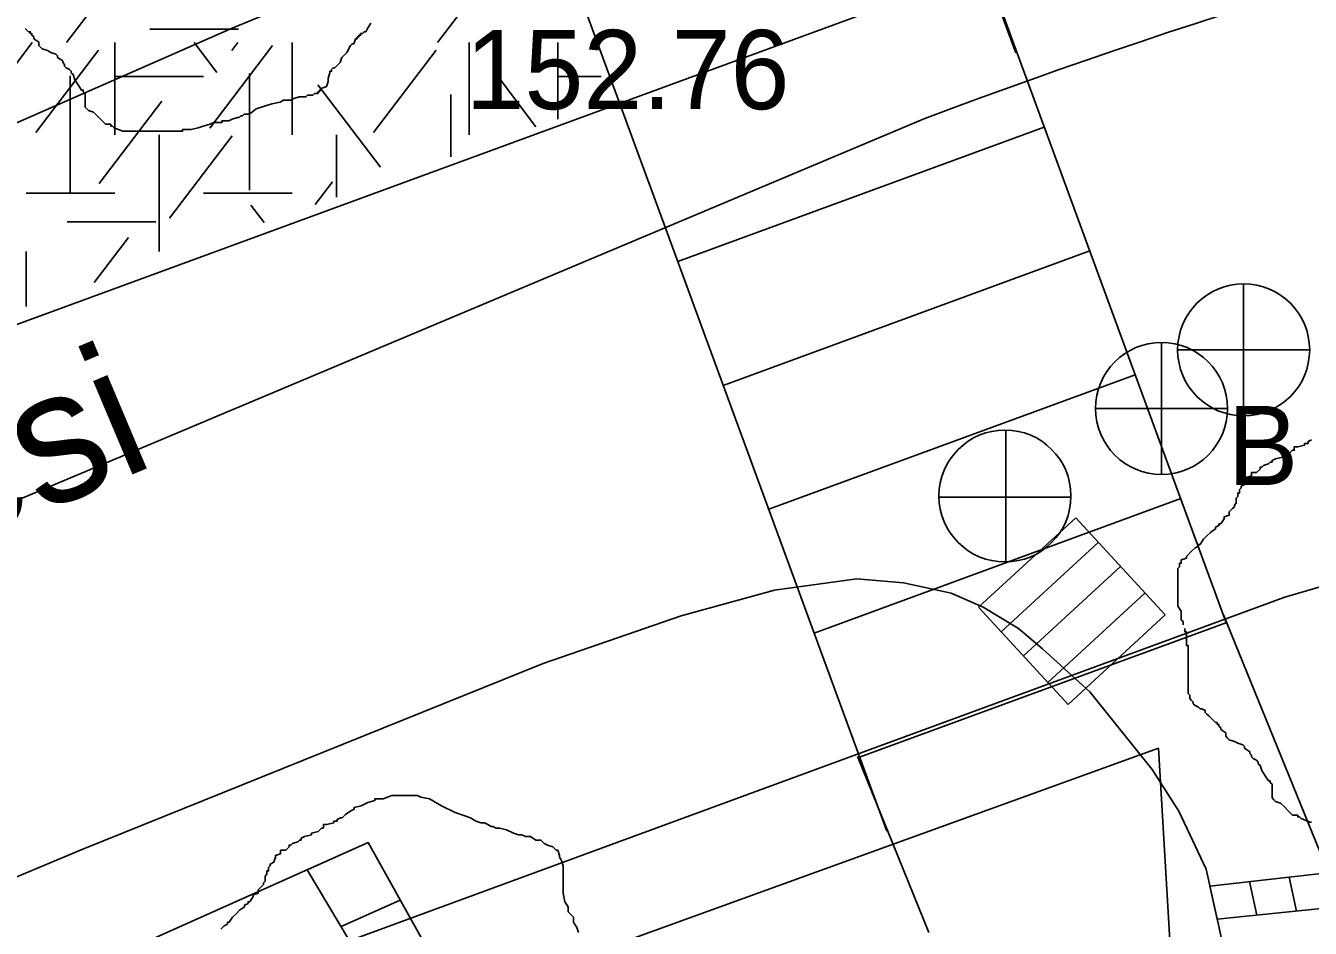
# Model space of a CAD drawing. Extents: x 419101 to 420177, y 4451541 to 4452254.
# Drawn here: x 419828.86 to 419848.32, y 4451817.27 to 4451830.95 of the extents above; entities that cross this region are included whole.
import ezdxf

# ---------------------------------------------------------------- set-up
doc = ezdxf.new("R2010")
doc.units = 0
for name, color, linetype in [('2_KADASTRO', 7, 'Continuous'), ('3_HALİHAZIR', 7, 'Continuous'), ('Level 3', 7, 'Continuous'), ('Level 41', 7, 'Continuous'), ('Level 60', 7, 'Continuous'), ('Level 62', 7, 'Continuous')]:
    doc.layers.add(name, color=color, linetype=linetype)

msp = doc.modelspace()

# ---------------------------------------------------------------- linework, layer by layer
at = {"layer": '2_KADASTRO'}
msp.add_lwpolyline([(419789.195, 4451663.821), (419792.466, 4451722.195), (419796.208, 4451788.966), (419796.952, 4451802.25), (419802.028, 4451804.087), (419846.019, 4451820.004), (419846.711, 4451808.426), (419850.52, 4451780.325), (419850.846, 4451775.043), (419851.91, 4451757.789), (419863.818, 4451701.263), (419862.735, 4451692.788), (419853.795, 4451660.742)], close=True, dxfattribs=at)
at = {"layer": '3_HALİHAZIR'}
for p, q in [((419847.31, 4451827.04), (419847.31, 4451825.04)), ((419846.066, 4451826.153), (419846.066, 4451824.153)), ((419846.31, 4451826.04), (419848.31, 4451826.04)), ((419845.066, 4451825.153), (419847.066, 4451825.153)), ((419843.709, 4451822.818), (419843.709, 4451824.818)), ((419842.689, 4451823.808), (419844.689, 4451823.808)), ((419844.766, 4451823.494), (419843.295, 4451822.14)), ((419844.766, 4451823.494), (419843.295, 4451822.14)), ((419846.121, 4451822.023), (419844.766, 4451823.494)), ((419846.121, 4451822.023), (419844.766, 4451823.494)), ((419843.636, 4451821.768), (419845.108, 4451823.123)), ((419843.972, 4451821.404), (419845.443, 4451822.758)), ((419844.343, 4451821.001), (419845.814, 4451822.355)), ((419843.295, 4451822.14), (419844.649, 4451820.668)), ((419843.295, 4451822.14), (419844.649, 4451820.668)), ((419844.649, 4451820.668), (419846.121, 4451822.023)), ((419844.649, 4451820.668), (419846.121, 4451822.023)), ((419847.398, 4451817.983), (419847.511, 4451817.472)), ((419847.997, 4451818.051), (419848.112, 4451817.534)), ((419833.636, 4451817.299), (419834.532, 4451817.7))]:
    msp.add_line(p, q, dxfattribs=at)
for points in [[(419841.024, 4451851.727), (419839.922, 4451837.507), (419839.676, 4451834.933), (419839.599, 4451834.673), (419839.324, 4451834.19), (419839.045, 4451833.925), (419838.738, 4451833.693), (419831.983, 4451830.915), (419822.667, 4451826.822)], [(419819.946, 4451814.381), (419829.721, 4451818.474), (419836.698, 4451821.289), (419838.786, 4451822.011), (419840.202, 4451822.4), (419841.449, 4451822.571), (419842.156, 4451822.512), (419842.877, 4451822.354), (419843.361, 4451822.14), (419843.897, 4451821.816), (419844.264, 4451821.509), (419844.979, 4451820.857), (419845.924, 4451819.679), (419846.329, 4451819.051), (419846.743, 4451818.168), (419847.007, 4451816.982)], [(419797.913, 4451802.315), (419813.395, 4451809.339), (419834.048, 4451818.574)]]:
    msp.add_lwpolyline(points, dxfattribs=at)
for points in [[(419833.122, 4451818.16), (419834.048, 4451818.574), (419834.973, 4451816.905), (419842.377, 4451813.448), (419845.895, 4451813.483), (419846.024, 4451812.471), (419842.025, 4451812.598), (419834.391, 4451816.032)], [(419846.911, 4451817.411), (419846.799, 4451817.915), (419852.975, 4451818.615), (419853.027, 4451818.037)]]:
    msp.add_lwpolyline(points, close=True, dxfattribs=at)
for centre in [(419847.31, 4451826.04), (419846.066, 4451825.153), (419843.694, 4451823.826)]:
    msp.add_circle(centre, 1, dxfattribs=at)
at = {"layer": 'Level 3'}
for points in [[(419830.353, 4451829.355), (419830.327, 4451829.355), (419830.197, 4451829.407), (419830.171, 4451829.433), (419830.145, 4451829.433), (419830.145, 4451829.459), (419830.067, 4451829.459), (419830.015, 4451829.511), (419829.938, 4451829.589), (419829.886, 4451829.641), (419829.808, 4451829.667), (419829.782, 4451829.693), (419829.756, 4451829.719), (419829.756, 4451829.745), (419829.756, 4451829.823), (419829.756, 4451829.901), (419829.756, 4451829.926), (419829.73, 4451829.952), (419829.73, 4451829.978), (419829.704, 4451829.978), (419829.652, 4451830.056), (419829.6, 4451830.134), (419829.574, 4451830.212), (419829.548, 4451830.238), (419829.548, 4451830.264), (419829.522, 4451830.29), (419829.471, 4451830.316), (419829.445, 4451830.342), (419829.445, 4451830.368), (419829.419, 4451830.394), (419829.419, 4451830.42), (419829.341, 4451830.472), (419829.341, 4451830.498), (419829.315, 4451830.524), (419829.237, 4451830.55), (419829.185, 4451830.576), (419829.107, 4451830.602), (419829.081, 4451830.628), (419829.056, 4451830.654), (419829.056, 4451830.68), (419829.056, 4451830.706), (419828.978, 4451830.757), (419828.978, 4451830.783), (419828.952, 4451830.809), (419828.952, 4451830.835), (419828.926, 4451830.835), (419828.926, 4451830.861), (419828.9, 4451830.861), (419828.874, 4451830.887), (419828.848, 4451830.913)], [(419834.088, 4451830.991), (419834.036, 4451830.913), (419834.01, 4451830.861), (419833.984, 4451830.861), (419833.958, 4451830.835), (419833.932, 4451830.835), (419833.932, 4451830.809), (419833.906, 4451830.809), (419833.906, 4451830.783), (419833.881, 4451830.783), (419833.881, 4451830.757), (419833.855, 4451830.757), (419833.829, 4451830.68), (419833.803, 4451830.68), (419833.777, 4451830.654), (419833.725, 4451830.55), (419833.647, 4451830.472), (419833.621, 4451830.394), (419833.543, 4451830.316), (419833.517, 4451830.316), (419833.491, 4451830.29), (419833.491, 4451830.264), (419833.465, 4451830.264), (419833.465, 4451830.238), (419833.44, 4451830.16), (419833.44, 4451830.108), (419833.414, 4451830.03), (419833.336, 4451830.004), (419833.336, 4451829.978), (419833.31, 4451829.978), (419833.31, 4451829.952), (419833.284, 4451829.952), (419833.284, 4451829.926), (419833.258, 4451829.926), (419833.232, 4451829.926), (419833.206, 4451829.901), (419833.18, 4451829.901), (419833.154, 4451829.901), (419833.128, 4451829.901), (419833.102, 4451829.875), (419833.076, 4451829.875), (419833.05, 4451829.875), (419833.024, 4451829.875), (419832.999, 4451829.875), (419832.921, 4451829.849), (419832.869, 4451829.823), (419832.791, 4451829.823), (419832.765, 4451829.823), (419832.713, 4451829.797), (419832.584, 4451829.771), (419832.35, 4451829.693), (419832.246, 4451829.615), (419832.168, 4451829.615), (419832.143, 4451829.589), (419832.117, 4451829.589), (419832.091, 4451829.563), (419832.065, 4451829.563), (419831.987, 4451829.537), (419831.935, 4451829.511), (419831.909, 4451829.511), (419831.883, 4451829.511), (419831.857, 4451829.511), (419831.831, 4451829.511), (419831.831, 4451829.485), (419831.805, 4451829.485), (419831.779, 4451829.485), (419831.702, 4451829.485), (419831.65, 4451829.459), (419831.546, 4451829.433), (419831.468, 4451829.407), (419831.364, 4451829.381), (419831.312, 4451829.381), (419831.286, 4451829.381), (419831.261, 4451829.381), (419831.235, 4451829.381), (419831.235, 4451829.355), (419831.209, 4451829.355), (419831.183, 4451829.355), (419831.157, 4451829.355), (419831.131, 4451829.355), (419831.105, 4451829.355), (419831.079, 4451829.355), (419831.053, 4451829.355), (419831.027, 4451829.355), (419831.001, 4451829.355), (419830.923, 4451829.355), (419830.871, 4451829.355), (419830.794, 4451829.355), (419830.742, 4451829.355), (419830.716, 4451829.355), (419830.69, 4451829.355), (419830.638, 4451829.355), (419830.56, 4451829.355), (419830.534, 4451829.355), (419830.482, 4451829.355), (419830.456, 4451829.355), (419830.404, 4451829.355), (419830.379, 4451829.355), (419830.353, 4451829.355)], [(419846.391, 4451821.872), (419846.391, 4451821.898), (419846.391, 4451821.923), (419846.365, 4451821.949), (419846.365, 4451821.975), (419846.365, 4451822.001), (419846.365, 4451822.027), (419846.365, 4451822.053), (419846.365, 4451822.079), (419846.313, 4451822.157), (419846.313, 4451822.235), (419846.313, 4451822.261), (419846.313, 4451822.339), (419846.313, 4451822.417), (419846.313, 4451822.443), (419846.313, 4451822.469), (419846.313, 4451822.495), (419846.313, 4451822.521), (419846.313, 4451822.547), (419846.313, 4451822.573), (419846.313, 4451822.599), (419846.313, 4451822.625), (419846.313, 4451822.651), (419846.313, 4451822.729), (419846.339, 4451822.754), (419846.339, 4451822.78), (419846.339, 4451822.806), (419846.365, 4451822.806), (419846.365, 4451822.832), (419846.365, 4451822.858), (419846.443, 4451822.884), (419846.443, 4451822.91), (419846.521, 4451822.988), (419846.573, 4451823.04), (419846.624, 4451823.066), (419846.624, 4451823.092), (419846.65, 4451823.092), (419846.702, 4451823.17), (419846.754, 4451823.222), (419846.806, 4451823.274), (419846.884, 4451823.326), (419846.884, 4451823.352), (419846.936, 4451823.378), (419846.936, 4451823.404), (419846.962, 4451823.404), (419847.014, 4451823.482), (419847.014, 4451823.508), (419847.091, 4451823.534), (419847.091, 4451823.559), (419847.091, 4451823.585), (419847.143, 4451823.637), (419847.169, 4451823.663), (419847.169, 4451823.689), (419847.195, 4451823.715), (419847.195, 4451823.741), (419847.195, 4451823.767), (419847.195, 4451823.793), (419847.221, 4451823.819), (419847.221, 4451823.845), (419847.221, 4451823.871), (419847.247, 4451823.871), (419847.247, 4451823.897), (419847.247, 4451823.923), (419847.273, 4451823.949), (419847.273, 4451823.975), (419847.325, 4451824.001), (419847.351, 4451824.079), (419847.351, 4451824.105), (419847.429, 4451824.131), (419847.429, 4451824.157), (419847.429, 4451824.183), (419847.506, 4451824.183), (419847.558, 4451824.235), (419847.558, 4451824.261), (419847.584, 4451824.261), (419847.61, 4451824.287), (419847.688, 4451824.313), (419847.714, 4451824.339), (419847.74, 4451824.339), (419847.74, 4451824.365), (419847.792, 4451824.39), (419847.896, 4451824.416), (419847.896, 4451824.442), (419847.999, 4451824.468), (419848.051, 4451824.52), (419848.077, 4451824.52), (419848.077, 4451824.546), (419848.077, 4451824.572), (419848.129, 4451824.572), (419848.233, 4451824.598), (419848.233, 4451824.624), (419848.259, 4451824.624), (419848.285, 4451824.624), (419848.285, 4451824.65), (419848.337, 4451824.676)], [(419848.337, 4451818.885), (419848.311, 4451818.885), (419848.181, 4451818.937), (419848.155, 4451818.963), (419848.129, 4451818.963), (419848.129, 4451818.989), (419848.051, 4451818.989), (419847.999, 4451819.041), (419847.922, 4451819.119), (419847.87, 4451819.171), (419847.792, 4451819.197), (419847.766, 4451819.223), (419847.74, 4451819.249), (419847.74, 4451819.275), (419847.74, 4451819.353), (419847.74, 4451819.431), (419847.74, 4451819.456), (419847.714, 4451819.482), (419847.714, 4451819.508), (419847.688, 4451819.508), (419847.636, 4451819.586), (419847.584, 4451819.664), (419847.558, 4451819.742), (419847.532, 4451819.768), (419847.532, 4451819.794), (419847.506, 4451819.82), (419847.455, 4451819.846), (419847.429, 4451819.872), (419847.429, 4451819.898), (419847.403, 4451819.924), (419847.403, 4451819.95), (419847.325, 4451820.002), (419847.325, 4451820.028), (419847.299, 4451820.054), (419847.221, 4451820.08), (419847.169, 4451820.106), (419847.091, 4451820.132), (419847.065, 4451820.158), (419847.04, 4451820.184), (419847.04, 4451820.21), (419847.04, 4451820.236), (419846.962, 4451820.287), (419846.962, 4451820.313), (419846.936, 4451820.339), (419846.936, 4451820.365), (419846.91, 4451820.365), (419846.91, 4451820.391), (419846.884, 4451820.391), (419846.858, 4451820.417), (419846.832, 4451820.443), (419846.806, 4451820.469), (419846.78, 4451820.495), (419846.754, 4451820.521), (419846.728, 4451820.547), (419846.728, 4451820.573), (419846.676, 4451820.599), (419846.65, 4451820.599), (419846.624, 4451820.625), (419846.573, 4451820.651), (419846.547, 4451820.677), (419846.547, 4451820.703), (419846.521, 4451820.729), (419846.495, 4451820.755), (419846.495, 4451820.781), (419846.495, 4451820.807), (419846.469, 4451820.833), (419846.469, 4451820.859), (419846.469, 4451820.885), (419846.469, 4451820.963), (419846.469, 4451821.015), (419846.469, 4451821.041), (419846.469, 4451821.067), (419846.469, 4451821.092), (419846.469, 4451821.118), (419846.469, 4451821.144), (419846.469, 4451821.17), (419846.469, 4451821.196), (419846.469, 4451821.222), (419846.469, 4451821.248), (419846.469, 4451821.274), (419846.469, 4451821.3), (419846.469, 4451821.326), (419846.469, 4451821.352), (419846.469, 4451821.378), (419846.469, 4451821.404), (419846.469, 4451821.43), (419846.469, 4451821.508), (419846.469, 4451821.534), (419846.469, 4451821.56), (419846.443, 4451821.56), (419846.443, 4451821.586), (419846.443, 4451821.612), (419846.443, 4451821.638), (419846.443, 4451821.664), (419846.443, 4451821.69), (419846.443, 4451821.716), (419846.443, 4451821.742), (419846.443, 4451821.768), (419846.417, 4451821.768), (419846.417, 4451821.794), (419846.417, 4451821.82)], [(419833.938, 4451819.131), (419834.042, 4451819.183), (419834.145, 4451819.209), (419834.145, 4451819.235), (419834.171, 4451819.235), (419834.197, 4451819.235), (419834.275, 4451819.235), (419834.405, 4451819.287), (419834.509, 4451819.287), (419834.586, 4451819.287), (419834.638, 4451819.287), (419834.716, 4451819.287), (419834.768, 4451819.287), (419834.794, 4451819.287), (419834.846, 4451819.261), (419834.976, 4451819.235), (419835.157, 4451819.131), (419835.365, 4451819.027), (419835.598, 4451818.949), (419835.676, 4451818.897), (419835.754, 4451818.871), (419835.806, 4451818.871), (419835.858, 4451818.845), (419835.909, 4451818.819), (419835.935, 4451818.819), (419835.987, 4451818.793), (419836.039, 4451818.793), (419836.143, 4451818.767), (419836.247, 4451818.715), (419836.324, 4451818.689), (419836.376, 4451818.689), (419836.428, 4451818.663), (419836.48, 4451818.663), (419836.506, 4451818.663), (419836.584, 4451818.612), (419836.662, 4451818.612), (419836.714, 4451818.56), (419836.765, 4451818.534), (419836.843, 4451818.508), (419836.895, 4451818.456), (419836.921, 4451818.456), (419836.947, 4451818.378), (419836.947, 4451818.352), (419836.973, 4451818.3), (419836.999, 4451818.222), (419836.999, 4451818.196), (419836.999, 4451818.118), (419836.999, 4451818.066), (419836.999, 4451817.988), (419836.999, 4451817.962), (419836.999, 4451817.884), (419836.999, 4451817.807), (419837.025, 4451817.677), (419837.077, 4451817.599), (419837.077, 4451817.521), (419837.155, 4451817.443), (419837.155, 4451817.365), (419837.206, 4451817.287), (419837.232, 4451817.209)], [(419831.811, 4451817.261), (419831.863, 4451817.313), (419831.914, 4451817.339), (419831.914, 4451817.365), (419831.94, 4451817.365), (419831.992, 4451817.443), (419832.044, 4451817.495), (419832.096, 4451817.547), (419832.174, 4451817.599), (419832.174, 4451817.625), (419832.226, 4451817.651), (419832.226, 4451817.677), (419832.252, 4451817.677), (419832.304, 4451817.755), (419832.304, 4451817.781), (419832.381, 4451817.807), (419832.381, 4451817.832), (419832.381, 4451817.858), (419832.433, 4451817.91), (419832.459, 4451817.936), (419832.459, 4451817.962), (419832.485, 4451817.988), (419832.485, 4451818.014), (419832.485, 4451818.04), (419832.485, 4451818.066), (419832.511, 4451818.092), (419832.511, 4451818.118), (419832.511, 4451818.144), (419832.537, 4451818.144), (419832.537, 4451818.17), (419832.537, 4451818.196), (419832.563, 4451818.222), (419832.563, 4451818.248), (419832.615, 4451818.274), (419832.641, 4451818.352), (419832.641, 4451818.378), (419832.719, 4451818.404), (419832.719, 4451818.43), (419832.719, 4451818.456), (419832.796, 4451818.456), (419832.848, 4451818.508), (419832.848, 4451818.534), (419832.874, 4451818.534), (419832.9, 4451818.56), (419832.978, 4451818.586), (419833.004, 4451818.612), (419833.03, 4451818.612), (419833.03, 4451818.638), (419833.082, 4451818.663), (419833.186, 4451818.689), (419833.186, 4451818.715), (419833.289, 4451818.741), (419833.341, 4451818.793), (419833.367, 4451818.793), (419833.367, 4451818.819), (419833.367, 4451818.845), (419833.419, 4451818.845), (419833.523, 4451818.871), (419833.523, 4451818.897), (419833.549, 4451818.897), (419833.575, 4451818.897), (419833.575, 4451818.923), (419833.627, 4451818.949), (419833.653, 4451818.949), (419833.704, 4451819.001), (419833.782, 4451819.053), (419833.834, 4451819.079), (419833.834, 4451819.105), (419833.938, 4451819.131)]]:
    msp.add_lwpolyline(points, dxfattribs=at)
at = {"layer": 'Level 41'}
for p, q in [((419829.477, 4451830.697), (419830.306, 4451831.788)), ((419835.097, 4451830.697), (419835.634, 4451831.403)), ((419830.739, 4451830.903), (419832.082, 4451830.903)), ((419828.64, 4451830.28), (419828.957, 4451830.697)), ((419830.206, 4451830.697), (419830.206, 4451829.299)), ((419831.755, 4451830.245), (419831.411, 4451830.697)), ((419831.648, 4451829.403), (419832.598, 4451830.653)), ((419831.981, 4451830.577), (419832.072, 4451830.697)), ((419832.892, 4451830.697), (419832.892, 4451829.299)), ((419835.578, 4451830.697), (419835.578, 4451829.299)), ((419836.921, 4451830.697), (419836.921, 4451829.539)), ((419836.921, 4451830.697), (419836.921, 4451829.539)), ((419829.011, 4451829.334), (419829.96, 4451830.584)), ((419834.125, 4451829.334), (419835.074, 4451830.584)), ((419832.248, 4451830.23), (419832.248, 4451828.463)), ((419836.588, 4451829.422), (419835.973, 4451830.232)), ((419829.531, 4451830.195), (419829.531, 4451828.428)), ((419830.206, 4451830.183), (419831.549, 4451830.183)), ((419834.232, 4451828.808), (419833.283, 4451830.057)), ((419836.921, 4451830.183), (419837.575, 4451830.183)), ((419835.296, 4451829.909), (419835.296, 4451828.966)), ((419829.971, 4451828.562), (419830.92, 4451829.812)), ((419830.878, 4451829.299), (419830.878, 4451827.532)), ((419831.037, 4451828.037), (419831.986, 4451829.287)), ((419833.564, 4451829.299), (419833.564, 4451828.355)), ((419833.244, 4451828.242), (419833.505, 4451828.585)), ((419828.863, 4451828.415), (419830.206, 4451828.415)), ((419831.549, 4451828.415), (419832.892, 4451828.415)), ((419832.472, 4451827.97), (419832.27, 4451828.235)), ((419829.487, 4451827.981), (419830.83, 4451827.981)), ((419829.896, 4451827.061), (419830.414, 4451827.744)), ((419828.863, 4451827.532), (419828.863, 4451826.697))]:
    msp.add_line(p, q, dxfattribs=at)
at = {"layer": 'Level 60'}
msp.add_line((419794.392, 4451809.323), (419842.479, 4451829.547), dxfattribs=at)
msp.add_arc((419876.549, 4451739.049), 96.699, 94.2053, 110.62966, dxfattribs=at)
at = {"layer": 'Level 62'}
for p, q in [((419838.315, 4451828.531), (419835.397, 4451836.48)), ((419843.858, 4451830.545), (419841.949, 4451835.746)), ((419847.041, 4451821.921), (419843.401, 4451831.835)), ((419847.041, 4451821.921), (419843.401, 4451831.835)), ((419847.041, 4451821.921), (419843.401, 4451831.835)), ((419800.177, 4451815.945), (419843.295, 4451831.774)), ((419844.288, 4451829.418), (419838.736, 4451827.38)), ((419844.288, 4451829.418), (419838.736, 4451827.38)), ((419844.288, 4451829.418), (419838.736, 4451827.38)), ((419841.905, 4451818.746), (419838.287, 4451828.603)), ((419841.905, 4451818.746), (419838.287, 4451828.603)), ((419841.905, 4451818.746), (419838.287, 4451828.603)), ((419844.978, 4451827.541), (419839.425, 4451825.503)), ((419844.978, 4451827.541), (419839.425, 4451825.503)), ((419844.978, 4451827.541), (419839.425, 4451825.503)), ((419845.667, 4451825.664), (419840.114, 4451823.625)), ((419845.667, 4451825.664), (419840.114, 4451823.625)), ((419845.667, 4451825.664), (419840.114, 4451823.625)), ((419846.356, 4451823.786), (419840.803, 4451821.748)), ((419846.356, 4451823.786), (419840.803, 4451821.748)), ((419846.356, 4451823.786), (419840.803, 4451821.748)), ((419762.727, 4451791.012), (419847.936, 4451822.291)), ((419847.053, 4451821.911), (419841.492, 4451819.87)), ((419847.053, 4451821.911), (419841.492, 4451819.87)), ((419847.053, 4451821.911), (419841.492, 4451819.87)), ((419848.882, 4451817.403), (419847.007, 4451822.026)), ((419848.882, 4451817.403), (419847.007, 4451822.026)), ((419848.882, 4451817.403), (419847.007, 4451822.026)), ((419842.538, 4451817.212), (419841.458, 4451819.876)), ((419842.538, 4451817.212), (419841.458, 4451819.876)), ((419842.538, 4451817.212), (419841.458, 4451819.876))]:
    msp.add_line(p, q, dxfattribs=at)
msp.add_arc((419902.659, 4451636.882), 193.317, 95.90854, 106.44394, dxfattribs=at)

# ---------------------------------------------------------------- texts
at = {"layer": '3_HALİHAZIR'}
for s, height, rotation, p in [('152.76 ', 1.2, 359.9971, (419835.521, 4451829.689)), ('Ýlkbahar Caddesi', 2, 22.8673, (419811.406, 4451816.11))]:
    msp.add_text(s, height=height, rotation=rotation, dxfattribs=at).set_placement(p)
msp.add_text('B', height=1.2, dxfattribs=at).set_placement((419847.066, 4451823.992))

doc.saveas('drawing.dxf')
